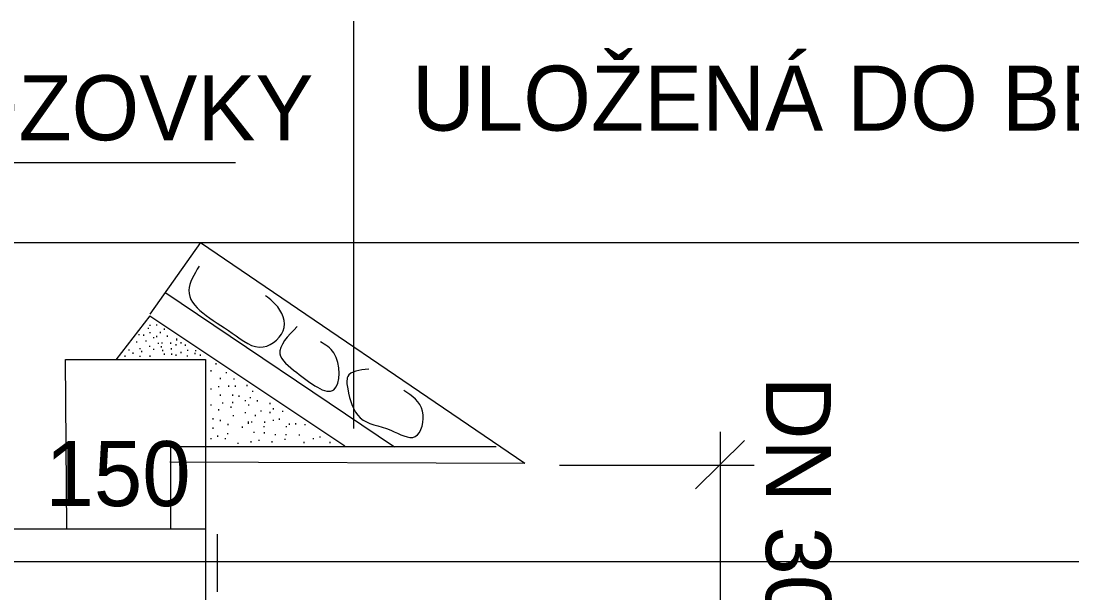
# Model space of a CAD drawing. Extents: x -463101.2 to -463058.2, y -1105044.4 to -1105011.4.
# Drawn here: x -463092.129 to -463088.835, y -1105018.196 to -1105016.402 of the extents above; entities that cross this region are included whole.
import ezdxf

# ---------------------------------------------------------------- set-up
doc = ezdxf.new("R2010")
doc.units = 0
doc.layers.add('Vrstva 14', color=7, linetype='Continuous')
doc.layers.add('Vrstva 57', color=7, linetype='Continuous')

msp = doc.modelspace()

# ---------------------------------------------------------------- linework, layer by layer
at = {"layer": 'Vrstva 14'}
for p, q in [((-463091.0868, -1105016.402), (-463091.0868, -1105017.6796)), ((-463091.5668, -1105017.0969), (-463091.7261, -1105017.3218)), ((-463091.5668, -1105017.0969), (-463086.3643, -1105017.0969)), ((-463091.6783, -1105017.2525), (-463090.959, -1105017.7379)), ((-463091.7254, -1105017.3266), (-463091.832, -1105017.4649)), ((-463091.7254, -1105017.3266), (-463091.114, -1105017.7345)), ((-463091.7305, -1105017.3641), (-463091.7305, -1105017.3677)), ((-463091.7305, -1105017.3641), (-463091.7305, -1105017.3677)), ((-463091.7261, -1105017.3548), (-463091.7261, -1105017.3584)), ((-463091.7043, -1105017.3539), (-463091.7043, -1105017.3575)), ((-463091.6804, -1105017.3667), (-463091.6804, -1105017.3704)), ((-463091.7602, -1105017.384), (-463091.7602, -1105017.3877)), ((-463091.746, -1105017.3854), (-463091.746, -1105017.389)), ((-463091.7261, -1105017.3778), (-463091.7261, -1105017.3815)), ((-463091.7145, -1105017.3934), (-463091.7145, -1105017.397)), ((-463091.7043, -1105017.3898), (-463091.7043, -1105017.3934)), ((-463091.6928, -1105017.3774), (-463091.6928, -1105017.381)), ((-463091.6711, -1105017.3889), (-463091.6711, -1105017.3926)), ((-463091.6423, -1105017.3973), (-463091.6423, -1105017.4009)), ((-463091.6423, -1105017.4009), (-463091.6423, -1105017.4045)), ((-463091.7913, -1105017.432), (-463091.7913, -1105017.4356)), ((-463091.7673, -1105017.4071), (-463091.7673, -1105017.4107)), ((-463091.7571, -1105017.428), (-463091.7571, -1105017.4316)), ((-463091.738, -1105017.404), (-463091.738, -1105017.4076)), ((-463091.7265, -1105017.4204), (-463091.7265, -1105017.4241)), ((-463091.7145, -1105017.4302), (-463091.7145, -1105017.4338)), ((-463091.6995, -1105017.4111), (-463091.6995, -1105017.4147)), ((-463091.6897, -1105017.4222), (-463091.6897, -1105017.4258)), ((-463091.6884, -1105017.4102), (-463091.6884, -1105017.4139)), ((-463091.6857, -1105017.4337), (-463091.6857, -1105017.4374)), ((-463091.6609, -1105017.4107), (-463091.6609, -1105017.4143)), ((-463091.6587, -1105017.4284), (-463091.6587, -1105017.432)), ((-463091.6587, -1105017.4284), (-463091.6587, -1105017.432)), ((-463091.6445, -1105017.416), (-463091.6445, -1105017.4196)), ((-463091.6285, -1105017.4093), (-463091.6285, -1105017.413)), ((-463091.6152, -1105017.4169), (-463091.6152, -1105017.4205)), ((-463091.6081, -1105017.4333), (-463091.6081, -1105017.4369)), ((-463091.5828, -1105017.4342), (-463091.5828, -1105017.4378)), ((-463091.9861, -1105017.9948), (-463091.9898, -1105017.4633)), ((-463091.8041, -1105017.4515), (-463091.8041, -1105017.4551)), ((-463091.7793, -1105017.4417), (-463091.7793, -1105017.4454)), ((-463091.7571, -1105017.4519), (-463091.7571, -1105017.4556)), ((-463091.7514, -1105017.4368), (-463091.7514, -1105017.4405)), ((-463091.7261, -1105017.4515), (-463091.7261, -1105017.4551)), ((-463091.6804, -1105017.4453), (-463091.6804, -1105017.4489)), ((-463091.6573, -1105017.4453), (-463091.6573, -1105017.4489)), ((-463091.6445, -1105017.4484), (-463091.6445, -1105017.452)), ((-463091.6285, -1105017.4399), (-463091.6285, -1105017.4436)), ((-463091.6086, -1105017.4506), (-463091.6086, -1105017.4542)), ((-463091.5846, -1105017.4431), (-463091.5846, -1105017.4467)), ((-463091.5678, -1105017.4484), (-463091.5678, -1105017.452)), ((-463091.5347, -1105017.4975), (-463091.5347, -1105017.5012)), ((-463091.5192, -1105017.4755), (-463091.5192, -1105017.4791)), ((-463091.5054, -1105017.5215), (-463091.5054, -1105017.5251)), ((-463091.4863, -1105017.503), (-463091.4863, -1105017.5066)), ((-463091.4628, -1105017.523), (-463091.4628, -1105017.5266)), ((-463091.5347, -1105017.5543), (-463091.5347, -1105017.558)), ((-463091.5108, -1105017.5471), (-463091.5108, -1105017.5507)), ((-463091.4791, -1105017.5453), (-463091.4791, -1105017.549)), ((-463091.4581, -1105017.5453), (-463091.4581, -1105017.549)), ((-463091.4212, -1105017.5432), (-463091.4212, -1105017.5469)), ((-463091.4039, -1105017.5616), (-463091.4039, -1105017.5652)), ((-463091.5049, -1105017.5737), (-463091.5049, -1105017.5774)), ((-463091.4978, -1105017.5981), (-463091.4978, -1105017.6017)), ((-463091.467, -1105017.5737), (-463091.467, -1105017.5774)), ((-463091.4662, -1105017.5965), (-463091.4662, -1105017.6002)), ((-463091.4464, -1105017.577), (-463091.4464, -1105017.5806)), ((-463091.4266, -1105017.5912), (-463091.4266, -1105017.5948)), ((-463091.4114, -1105017.5814), (-463091.4114, -1105017.585)), ((-463091.3888, -1105017.5916), (-463091.3888, -1105017.5952)), ((-463091.3493, -1105017.6), (-463091.3493, -1105017.6037)), ((-463091.5347, -1105017.6045), (-463091.5347, -1105017.6081)), ((-463091.5108, -1105017.6199), (-463091.5108, -1105017.6235)), ((-463091.472, -1105017.6115), (-463091.472, -1105017.6151)), ((-463091.4266, -1105017.6285), (-463091.4266, -1105017.6321)), ((-463091.4163, -1105017.6045), (-463091.4163, -1105017.6081)), ((-463091.3781, -1105017.6236), (-463091.3781, -1105017.6272)), ((-463091.3493, -1105017.628), (-463091.3493, -1105017.6316)), ((-463091.3391, -1105017.6165), (-463091.3391, -1105017.6201)), ((-463091.3098, -1105017.6244), (-463091.3098, -1105017.6281)), ((-463091.5285, -1105017.648), (-463091.5285, -1105017.6516)), ((-463091.5054, -1105017.6533), (-463091.5054, -1105017.6569)), ((-463091.481, -1105017.6657), (-463091.481, -1105017.6693)), ((-463091.4646, -1105017.6378), (-463091.4646, -1105017.6414)), ((-463091.4176, -1105017.6581), (-463091.4176, -1105017.6617)), ((-463091.4176, -1105017.6617), (-463091.4176, -1105017.6654)), ((-463091.4065, -1105017.6577), (-463091.4065, -1105017.6614)), ((-463091.3959, -1105017.6373), (-463091.3959, -1105017.6409)), ((-463091.3662, -1105017.6582), (-463091.3662, -1105017.6618)), ((-463091.3391, -1105017.6524), (-463091.3391, -1105017.656)), ((-463091.3205, -1105017.6488), (-463091.3205, -1105017.6525)), ((-463091.2886, -1105017.6648), (-463091.2886, -1105017.6685)), ((-463091.2695, -1105017.6635), (-463091.2695, -1105017.6671)), ((-463091.2398, -1105017.6662), (-463091.2398, -1105017.6698)), ((-463091.5285, -1105017.6772), (-463091.5285, -1105017.6809)), ((-463091.4819, -1105017.6946), (-463091.4819, -1105017.6982)), ((-463091.4362, -1105017.6741), (-463091.4362, -1105017.6778)), ((-463091.3994, -1105017.6901), (-463091.3994, -1105017.6937)), ((-463091.3688, -1105017.6728), (-463091.3688, -1105017.6764)), ((-463091.3671, -1105017.6919), (-463091.3671, -1105017.6955)), ((-463091.3333, -1105017.6977), (-463091.3333, -1105017.7013)), ((-463091.2992, -1105017.6977), (-463091.2992, -1105017.7013)), ((-463091.2983, -1105017.6728), (-463091.2983, -1105017.6764)), ((-463091.258, -1105017.6985), (-463091.258, -1105017.7022)), ((-463089.9382, -1105017.6909), (-463089.9382, -1105018.4471)), ((-463091.5347, -1105017.7101), (-463091.5347, -1105017.7137)), ((-463091.5134, -1105017.7021), (-463091.5134, -1105017.7057)), ((-463091.4899, -1105017.7101), (-463091.4899, -1105017.7137)), ((-463091.45, -1105017.7247), (-463091.45, -1105017.7284)), ((-463091.4092, -1105017.7203), (-463091.4092, -1105017.7239)), ((-463091.3839, -1105017.7154), (-463091.3839, -1105017.719)), ((-463091.3435, -1105017.7203), (-463091.3435, -1105017.7239)), ((-463091.3027, -1105017.7123), (-463091.3027, -1105017.7159)), ((-463091.2429, -1105017.7221), (-463091.2429, -1105017.7257)), ((-463091.2132, -1105017.7101), (-463091.2132, -1105017.7137)), ((-463091.1923, -1105017.7052), (-463091.1923, -1105017.7088)), ((-463091.1613, -1105017.7221), (-463091.1613, -1105017.7257)), ((-463089.8615, -1105017.7181), (-463090.015, -1105017.8689)), ((-463091.5514, -1105017.7524), (-463091.5514, -1105018.4595)), ((-463091.6633, -1105017.7847), (-463090.5506, -1105017.7885)), ((-463090.4421, -1105017.7955), (-463089.8313, -1105017.7955)), ((-463092.6812, -1105017.9948), (-463091.5514, -1105017.9948)), ((-463091.5145, -1105018.0119), (-463091.5145, -1105018.1919)), ((-463092.6778, -1105018.0969), (-463086.3643, -1105018.0969))]:
    msp.add_line(p, q, dxfattribs=at)
for points in [[(-463092.7378, -1105017.0969), (-463092.7378, -1105016.8455), (-463091.457, -1105016.8455)], [(-463092.7378, -1105017.0969), (-463091.5668, -1105017.0969), (-463090.5506, -1105017.7885)], [(-463091.9898, -1105017.4633), (-463091.5514, -1105017.4633), (-463091.5514, -1105017.7524)], [(-463090.6406, -1105017.7381), (-463091.6609, -1105017.7381), (-463091.6609, -1105017.9948)]]:
    msp.add_lwpolyline(points, dxfattribs=at)
for points in [[(-463091.571, -1105017.1708), (-463091.6031, -1105017.2465), (-463091.4677, -1105017.3806), (-463091.3701, -1105017.4243), (-463091.3046, -1105017.3631), (-463091.341, -1105017.2815), (-463091.3628, -1105017.264)], [(-463091.2638, -1105017.3602), (-463091.3177, -1105017.4461), (-463091.2653, -1105017.5044), (-463091.1488, -1105017.5583), (-463091.1488, -1105017.4432), (-463091.191, -1105017.4082)], [(-463091.0397, -1105017.4941), (-463091.1054, -1105017.5175), (-463091.1054, -1105017.5557), (-463091.0663, -1105017.6465), (-463090.9706, -1105017.6856), (-463090.8941, -1105017.7056), (-463090.8708, -1105017.6257), (-463090.9299, -1105017.5607)]]:
    msp.add_spline(points, degree=3, dxfattribs=at)

# ---------------------------------------------------------------- texts
at = {"layer": 'Vrstva 57'}
for s, p in [('ULOŽENÁ DO BET. LOŽE', (-463090.9038, -1105016.7458)), ('KÓTA VOZOVKY', (-463093.3501, -1105016.7761)), ('DRENÁŽNÍ POTRUBÍ DN 150', (-463095.2811, -1105017.9236))]:
    msp.add_text(s, height=0.204, dxfattribs=at).set_placement(p)
msp.add_text('DN 300', height=0.204, rotation=270, dxfattribs=at).set_placement((-463089.7948, -1105017.5174))

doc.saveas('drawing.dxf')
